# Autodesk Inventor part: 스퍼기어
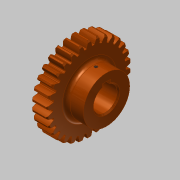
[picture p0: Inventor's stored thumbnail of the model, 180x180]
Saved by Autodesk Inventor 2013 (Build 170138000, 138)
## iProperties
Created: 2019-01
Part Number: 스퍼기어
Material: 알루미늄 6061
Document SubType Name: Modeling
Designer: mduedu
Density: 1 g/cm^3
Author: mduedu
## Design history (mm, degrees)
sketch "스케치1"
  geometry: C1 r 27.5 at (0, 0); 1 further point
  constraints: 1 centre point, 1 coincident
  dimensions: "d0" = 55 diameter of C1
extrude "돌출1" new body sketch "스케치1" stored distance "d2" = 12; taper "d3" = 0 deg
sketch "스케치2" dims "d4" = 60
  geometry: L1 (0, 0)-(-32, 0); L2 (0, 0)-(0, 32); L3 (-0.57, 0)-(-0.57, 31.995); L4 (-1.57, 0)-(-1.57, 31.961); L5 (-2.07, 0)-(-2.07, 31.933); C1 r 27.5 at (0, 0); A1 r 32 centre (0, 0) between (-32, 0) and (0, 32); A2 r 9.292 centre (7.208, 26.911) between (-0.57, 31.995) and (-2.07, 27.422); A3 r 9.292 centre (-7.208, 26.911) between (2.07, 27.422) and (0.57, 31.995); A4 r 27.5 centre (0, 0) between (2.07, 27.422) and (-2.07, 27.422); A5 r 32 centre (0, 0) between (0.57, 31.995) and (-0.57, 31.995); 3 further points
  constraints: 14 point on circle, 10 end point, 6 centre point, 5 coincident, 5 point on line, 3 symmetric about line, 2 parallel, 2 perpendicular, 1 horizontal, 7 other
  dimensions: "d6" = 64 diameter of A1; "d7" = 0.5 distance between parallel lines of L4 L5; "d8" = 1 distance between parallel lines of L3 L4; "d9" = 1.57 distance between parallel lines of L2 L4
extrude "돌출2" join sketch "스케치2" stored distance "d10" = 0; taper "d11" = 0 deg
chamfer "모따기1" distance "d12" = 1; stored, may be unused: second distance "d13" = 2, angle "d14" = 45 deg
fillet "모깎기1" dims "d15" = 0.5
sketch "스케치3"
  geometry: C1 r 17.5 at (0, 0); 1 further point
  constraints: 1 centre point, 1 coincident
  dimensions: "d19" = 35 diameter of C1
extrude "돌출3" join sketch "스케치3" distance "d20" = 13; taper "d21" = 0 deg
sketch "스케치4"
  geometry: L1 (-3, 8.485)-(3, 8.485); L2 (3, 8.485)-(3, 11.8); L3 (3, 11.8)-(-3, 11.8); L4 (-3, 11.8)-(-3, 8.485); A1 r 9 centre (0, 0) between (-3, 8.485) and (3, 8.485); 1 further point
  constraints: 8 end point, 2 parallel, 2 point on circle, 1 centre point, 1 coincident, 1 horizontal, 1 perpendicular
  dimensions: "d22" = 18 diameter of A1; "d23" = 6 distance of L2.end L3.end; "d24" = 20.8 dimension on A1 L3
extrude "돌출4" cut sketch "스케치4" stored distance "d25" = 13; taper "d26" = 0 deg
sketch "스케치5"
  geometry: C1 r 15 at (0, 0); C2 r 22.5 at (0, 0); 1 further point
  constraints: 2 centre point, 2 coincident
  dimensions: "d33" = 30 diameter of C1; "d34" = 45 diameter of C2
extrude "돌출5" cut sketch "스케치5" distance "d30" = 6; taper "d31" = 0 deg
fillet "모깎기2" dims "d32" = 3
node "작업 평면1"
sketch "스케치6"
  geometry: L1 (17.5, 13)-(-17.5, 13) reference; 2 further points
  constraints: 1 vertical alignment
  dimensions: "d35" = 8 distance from line of point (0, 5) L1
hole "구멍1" sketch "스케치6" at (0, 5) diameter "d36" = 2.459; stored, may be unused: countersink angle "d40" = 90 deg, drill point angle "d42" = 118 deg; dims "d37" = 6, "d38" = 4, "d39" = 2, "d41" = 8
fillet "모깎기3" dims "d43" = 3
chamfer "모따기2" distance "d44" = 1; stored, may be unused: second distance "d45" = 2, angle "d46" = 45 deg
node "솔리드1"
pattern_circular "원형 패턴1" dims "d17" = 360 deg
